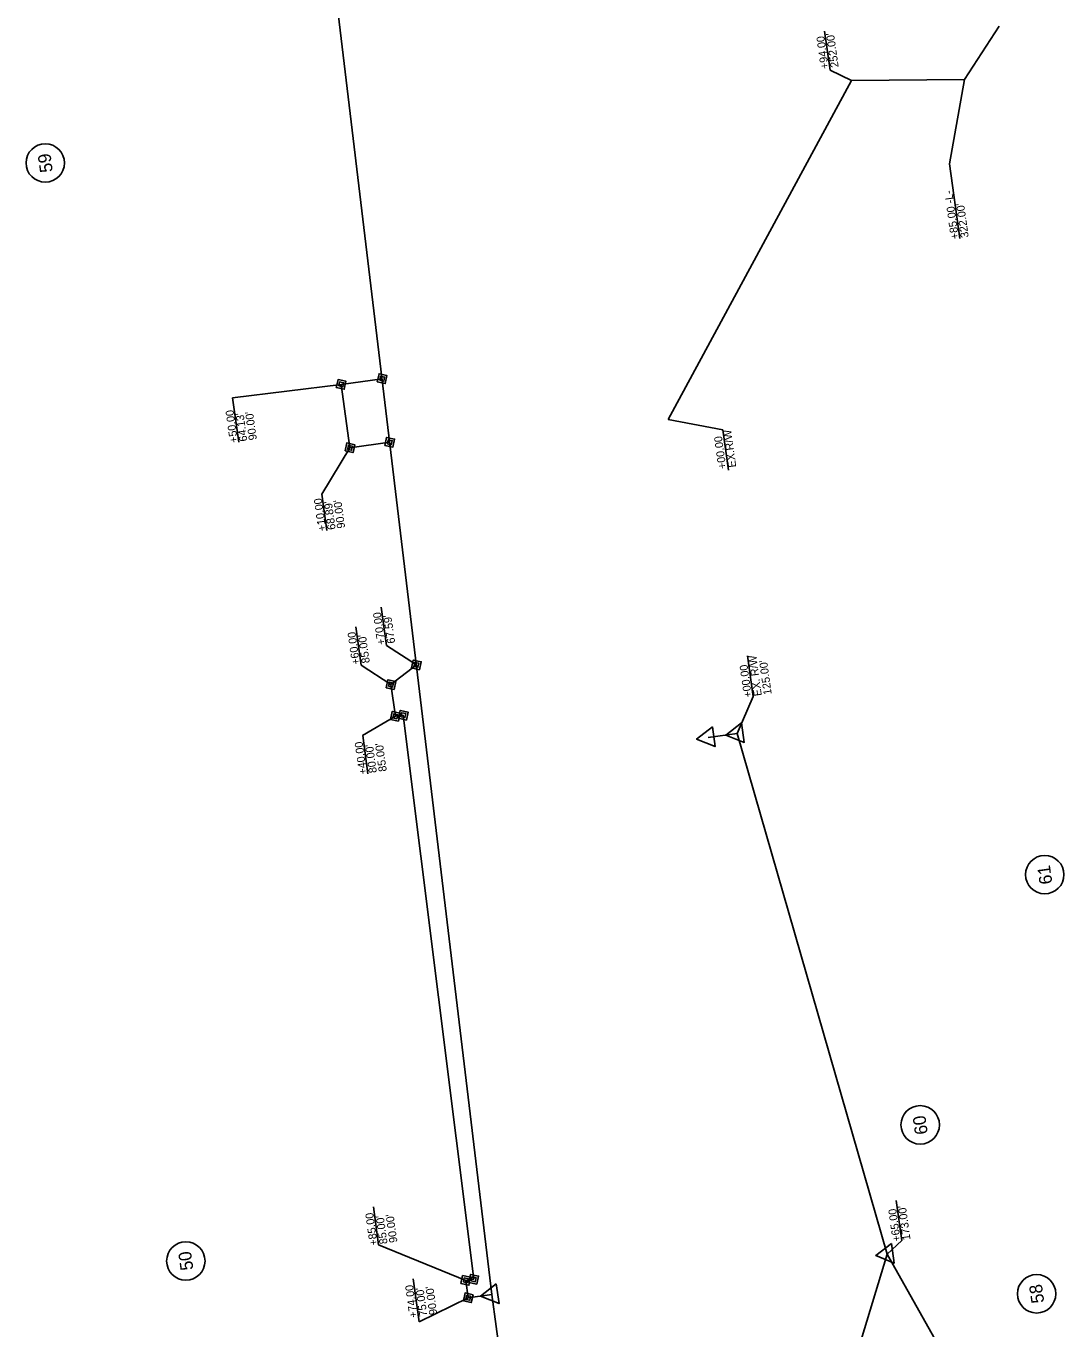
# Model space of a CAD drawing. Extents: x 474184 to 481900, y 489262 to 505659.
# Drawn here: x 477644 to 478293, y 498047 to 498861 of the extents above; entities that cross this region are included whole.
import ezdxf

# ---------------------------------------------------------------- set-up
doc = ezdxf.new("R2010")
doc.units = 0
for name, color, linetype in [('Prop Drainage Structure Drop Inlet Grate 2 Wide Slots and Sag Grates 840 22 CELL', 7, 'Continuous'), ('Prop Drainage Structure Outlet Berm Ditch 850 10 Label', 7, 'Continuous'), ('Prop Drainage Structure Pipe CSP 15in', 7, 'Continuous'), ('Prop Drainage Structure Pipe RCP 18in Class IV', 7, 'Continuous'), ('Prop Drainage Structure Pipe RCP 18in Class IV Label', 7, 'Continuous'), ('Prop Drainage Structure Pipe Side Drain 15in Label', 7, 'Continuous'), ('Prop Drainage Structure Pipe Stub Out CELL', 7, 'Continuous'), ('Prop Drainage Structure Plot Symbol 50 Scale', 7, 'Continuous'), ('Prop Earthen Structure Base Ditch Lateral Detail Label', 7, 'Continuous'), ('Prop Earthen Structure False Sump CELL', 7, 'Continuous'), ('Prop Earthen Structure False Sump Label', 7, 'Continuous')]:
    doc.layers.add(name, color=color, linetype=linetype)

msp = doc.modelspace()

# ---------------------------------------------------------------- linework, layer by layer
at = {"layer": 'Prop Drainage Structure Drop Inlet Grate 2 Wide Slots and Sag Grates 840 22 CELL'}
for p, q in [((477841.25, 498637.05), (477866.87, 498640.61)), ((477846.77, 498597.43), (477841.25, 498637.05)), ((477871.64, 498600.89), (477846.77, 498597.43))]:
    msp.add_line(p, q, dxfattribs=at)
at = {"layer": 'Prop Drainage Structure Outlet Berm Ditch 850 10 Label'}
for p, q in [((477872.4, 498449.55), (477888.26, 498461.86)), ((477875.15, 498429.74), (477872.4, 498449.55)), ((477880.11, 498430.43), (477875.15, 498429.74)), ((477924.08, 498078.13), (477880.11, 498430.43)), ((477919.13, 498077.44), (477924.08, 498078.13)), ((477920.65, 498066.55), (477919.13, 498077.44)), ((477935.51, 498068.61), (477920.65, 498066.55))]:
    msp.add_line(p, q, dxfattribs=at)
at = {"layer": 'Prop Drainage Structure Pipe CSP 15in'}
for p, q in [((477656.41, 498775.34), (477656.41, 498775.34)), ((478280.85, 498330.86), (478280.85, 498330.86)), ((478280.85, 498330.86), (478280.85, 498330.86)), ((478203.04, 498174.57), (478203.04, 498174.57)), ((477744.23, 498089.53), (477744.23, 498089.53)), ((478275.78, 498069.05), (478275.78, 498069.05))]:
    msp.add_line(p, q, dxfattribs=at)
for centre in [(477656.41, 498775.34), (478280.85, 498330.86), (478280.85, 498330.86), (478203.04, 498174.57), (477744.23, 498089.53), (478275.78, 498069.05)]:
    msp.add_circle(centre, 12, dxfattribs=at)
at = {"layer": 'Prop Drainage Structure Pipe RCP 18in Class IV'}
for p, q in [((477866.87, 498640.61), (477866.87, 498640.61)), ((477841.25, 498637.05), (477841.25, 498637.05)), ((477871.64, 498600.89), (477871.64, 498600.89)), ((477846.77, 498597.43), (477846.77, 498597.43)), ((477888.26, 498461.86), (477888.26, 498461.86)), ((477872.4, 498449.55), (477872.4, 498449.55)), ((477875.15, 498429.74), (477875.15, 498429.74)), ((477880.11, 498430.43), (477880.11, 498430.43)), ((478088.66, 498419.07), (478088.66, 498419.07)), ((478070.47, 498416.54), (478070.47, 498416.54)), ((478182.38, 498093.88), (478182.38, 498093.88)), ((477919.13, 498077.44), (477919.13, 498077.44)), ((477924.08, 498078.13), (477924.08, 498078.13)), ((477935.51, 498068.61), (477935.51, 498068.61)), ((477920.65, 498066.55), (477920.65, 498066.55))]:
    msp.add_line(p, q, dxfattribs=at)
for points in [[(478073.18, 498423.22), (478074.9, 498410.86), (478063.33, 498415.53)], [(478091.38, 498425.75), (478093.09, 498413.39), (478081.52, 498418.06)], [(478185.09, 498100.57), (478186.81, 498088.21), (478175.24, 498092.88)], [(477938.22, 498075.3), (477939.93, 498062.94), (477928.36, 498067.61)]]:
    msp.add_lwpolyline(points, close=True, dxfattribs=at)
at = {"layer": 'Prop Drainage Structure Pipe RCP 18in Class IV Label'}
for points in [[(477838.23, 498635.11), (477839.31, 498640.08), (477844.28, 498638.99), (477843.2, 498634.02)], [(477839.74, 498636.08), (477840.28, 498638.56), (477842.77, 498638.02), (477842.23, 498635.53)], [(477863.85, 498638.67), (477864.93, 498643.65), (477869.9, 498642.56), (477868.82, 498637.58)], [(477865.36, 498639.64), (477865.9, 498642.13), (477868.39, 498641.59), (477867.85, 498639.1)], [(477843.74, 498595.49), (477844.82, 498600.46), (477849.8, 498599.37), (477848.71, 498594.4)], [(477845.25, 498596.46), (477845.8, 498598.95), (477848.28, 498598.4), (477847.74, 498595.92)], [(477868.61, 498598.95), (477869.7, 498603.92), (477874.67, 498602.84), (477873.59, 498597.86)], [(477870.13, 498599.92), (477870.67, 498602.41), (477873.16, 498601.86), (477872.61, 498599.38)], [(477885.23, 498459.91), (477886.32, 498464.89), (477891.29, 498463.8), (477890.21, 498458.83)], [(477886.75, 498460.88), (477887.29, 498463.37), (477889.78, 498462.83), (477889.23, 498460.34)], [(477869.37, 498447.61), (477870.45, 498452.58), (477875.43, 498451.5), (477874.34, 498446.52)], [(477870.88, 498448.58), (477871.42, 498451.07), (477873.91, 498450.52), (477873.37, 498448.04)], [(477872.12, 498427.8), (477873.21, 498432.77), (477878.18, 498431.69), (477877.1, 498426.71)], [(477873.64, 498428.77), (477874.18, 498431.26), (477876.67, 498430.71), (477876.12, 498428.23)], [(477877.08, 498428.49), (477878.16, 498433.46), (477883.13, 498432.38), (477882.05, 498427.4)], [(477878.59, 498429.46), (477879.13, 498431.95), (477881.62, 498431.4), (477881.08, 498428.92)], [(477916.1, 498075.5), (477917.19, 498080.47), (477922.16, 498079.39), (477921.08, 498074.41)], [(477917.62, 498076.47), (477918.16, 498078.96), (477920.65, 498078.41), (477920.1, 498075.93)], [(477921.06, 498076.19), (477922.14, 498081.16), (477927.11, 498080.08), (477926.03, 498075.1)], [(477922.57, 498077.16), (477923.11, 498079.65), (477925.6, 498079.1), (477925.06, 498076.62)], [(477917.62, 498064.6), (477918.71, 498069.58), (477923.68, 498068.49), (477922.59, 498063.52)], [(477919.13, 498065.58), (477919.68, 498068.06), (477922.16, 498067.52), (477921.62, 498065.03)]]:
    msp.add_lwpolyline(points, close=True, dxfattribs=at)
at = {"layer": 'Prop Drainage Structure Pipe Side Drain 15in Label'}
for p, q in [((477935.51, 498068.61), (477825.37, 498985.31)), ((478088.66, 498419.07), (478070.47, 498416.54)), ((478182.38, 498093.88), (478088.66, 498419.07)), ((478151.97, 497993.74), (478182.38, 498093.88)), ((477986.86, 497688.92), (477935.51, 498068.61))]:
    msp.add_line(p, q, dxfattribs=at)
at = {"layer": 'Prop Drainage Structure Pipe Stub Out CELL'}
for p, q in [((478230.71, 498827.55), (478252.33, 498860.85)), ((478045.66, 498615.01), (478160.14, 498826.82)), ((478160.14, 498826.82), (478230.71, 498827.55)), ((478258.84, 497957.86), (478182.38, 498093.88))]:
    msp.add_line(p, q, dxfattribs=at)
at = {"layer": 'Prop Drainage Structure Plot Symbol 50 Scale'}
for p, q in [((478095.11, 498467.57), (478098.66, 498442.06)), ((478188.05, 498127.42), (478191.55, 498102.25)), ((477886.36, 498078.39), (477890.09, 498051.57))]:
    msp.add_line(p, q, dxfattribs=at)
for points in [[(478098.66, 498442.06), (478088.66, 498419.07)], [(478191.55, 498102.25), (478182.38, 498093.88)], [(477890.09, 498051.57), (477920.65, 498066.55)]]:
    msp.add_lwpolyline(points, dxfattribs=at)
at = {"layer": 'Prop Earthen Structure Base Ditch Lateral Detail Label'}
for p, q in [((477866.33, 498497.88), (477869.65, 498474.06)), ((477850.47, 498485.57), (477853.78, 498461.75)), ((477854.73, 498417.66), (477858.04, 498393.84)), ((477861.39, 498123.43), (477864.7, 498099.61))]:
    msp.add_line(p, q, dxfattribs=at)
for points in [[(477869.65, 498474.06), (477888.26, 498461.86)], [(477853.78, 498461.75), (477872.4, 498449.55)], [(477854.71, 498417.76), (477875.15, 498429.74)], [(477864.7, 498099.61), (477919.13, 498077.44)]]:
    msp.add_lwpolyline(points, dxfattribs=at)
at = {"layer": 'Prop Earthen Structure False Sump CELL'}
for p, q in [((477773.4, 498628.66), (477777.26, 498600.96)), ((477829.27, 498568.45), (477832.42, 498545.82))]:
    msp.add_line(p, q, dxfattribs=at)
for points in [[(477773.4, 498628.66), (477841.25, 498637.05)], [(477829.27, 498568.45), (477846.77, 498597.43)]]:
    msp.add_lwpolyline(points, dxfattribs=at)
at = {"layer": 'Prop Earthen Structure False Sump Label'}
for p, q in [((478146.7, 498833.22), (478143.29, 498857.72)), ((478160.14, 498826.82), (478146.7, 498833.22)), ((478221.31, 498774.89), (478227.82, 498728.18)), ((478079.67, 498608.69), (478083.19, 498583.38))]:
    msp.add_line(p, q, dxfattribs=at)
for points in [[(478221.31, 498774.89), (478230.71, 498827.55)], [(478079.67, 498608.69), (478045.66, 498615.01)]]:
    msp.add_lwpolyline(points, dxfattribs=at)

# ---------------------------------------------------------------- texts
at = {"layer": 'Prop Drainage Structure Pipe CSP 15in'}
for s, p in [('59', (477661.2, 498769.92)), ('61', (478285.66, 498325.33)), ('60', (478207.85, 498169.04)), ('50', (477749, 498084.22)), ('58', (478280.57, 498063.69))]:
    msp.add_text(s, height=8, rotation=97.92268, dxfattribs=at).set_placement(p)
at = {"layer": 'Prop Drainage Structure Plot Symbol 50 Scale'}
for s, p in [('EX. R/W', (478104.11, 498442.7)), ('+00.00', (478097.92, 498441.84)), ("125.00'", (478110.3, 498443.56)), ('+65.00', (478190.83, 498102.03)), ("173.00'", (478197.02, 498102.89)), ('+74.00', (477888.97, 498054.47)), ("75.00'", (477895.16, 498055.34)), ("90.00'", (477901.35, 498056.2))]:
    msp.add_text(s, height=5, rotation=97.92268, dxfattribs=at).set_placement(p)
at = {"layer": 'Prop Earthen Structure Base Ditch Lateral Detail Label'}
for s, p in [('+70.00', (477868.87, 498474.64)), ("67.59' ", (477875.06, 498475.5)), ('+60.00', (477853, 498462.34)), ("85.00'", (477859.2, 498463.2)), ('+40.00', (477857.42, 498393.76)), ("80.00'", (477863.61, 498394.62)), ("85.00'", (477869.8, 498395.48)), ('+85.00', (477864.09, 498099.53)), ("90.00'", (477876.47, 498101.25)), ("85.00'", (477870.28, 498100.39))]:
    msp.add_text(s, height=5, rotation=97.92268, dxfattribs=at).set_placement(p)
at = {"layer": 'Prop Earthen Structure False Sump CELL'}
for s, p in [('+50.00', (477776.76, 498600.89)), ("64.13'", (477782.7, 498601.72)), ("90.00'", (477788.65, 498602.54)), ('+10.00', (477831.93, 498545.75)), ("68.89'", (477837.87, 498546.58)), ("90.00'", (477843.81, 498547.41))]:
    msp.add_text(s, height=5, rotation=97.92268, dxfattribs=at).set_placement(p)
at = {"layer": 'Prop Earthen Structure False Sump Label'}
for s, p in [('+94.00', (478145.91, 498834.43)), ("252.00' ", (478152.11, 498835.29)), ('+85.00 -L-', (478227.2, 498728.09)), ("322.00'", (478233.39, 498728.95)), ('EX.R/W', (478088.15, 498585.45)), ('+00.00', (478081.96, 498584.58))]:
    msp.add_text(s, height=5, rotation=97.92268, dxfattribs=at).set_placement(p)

doc.saveas('drawing.dxf')
